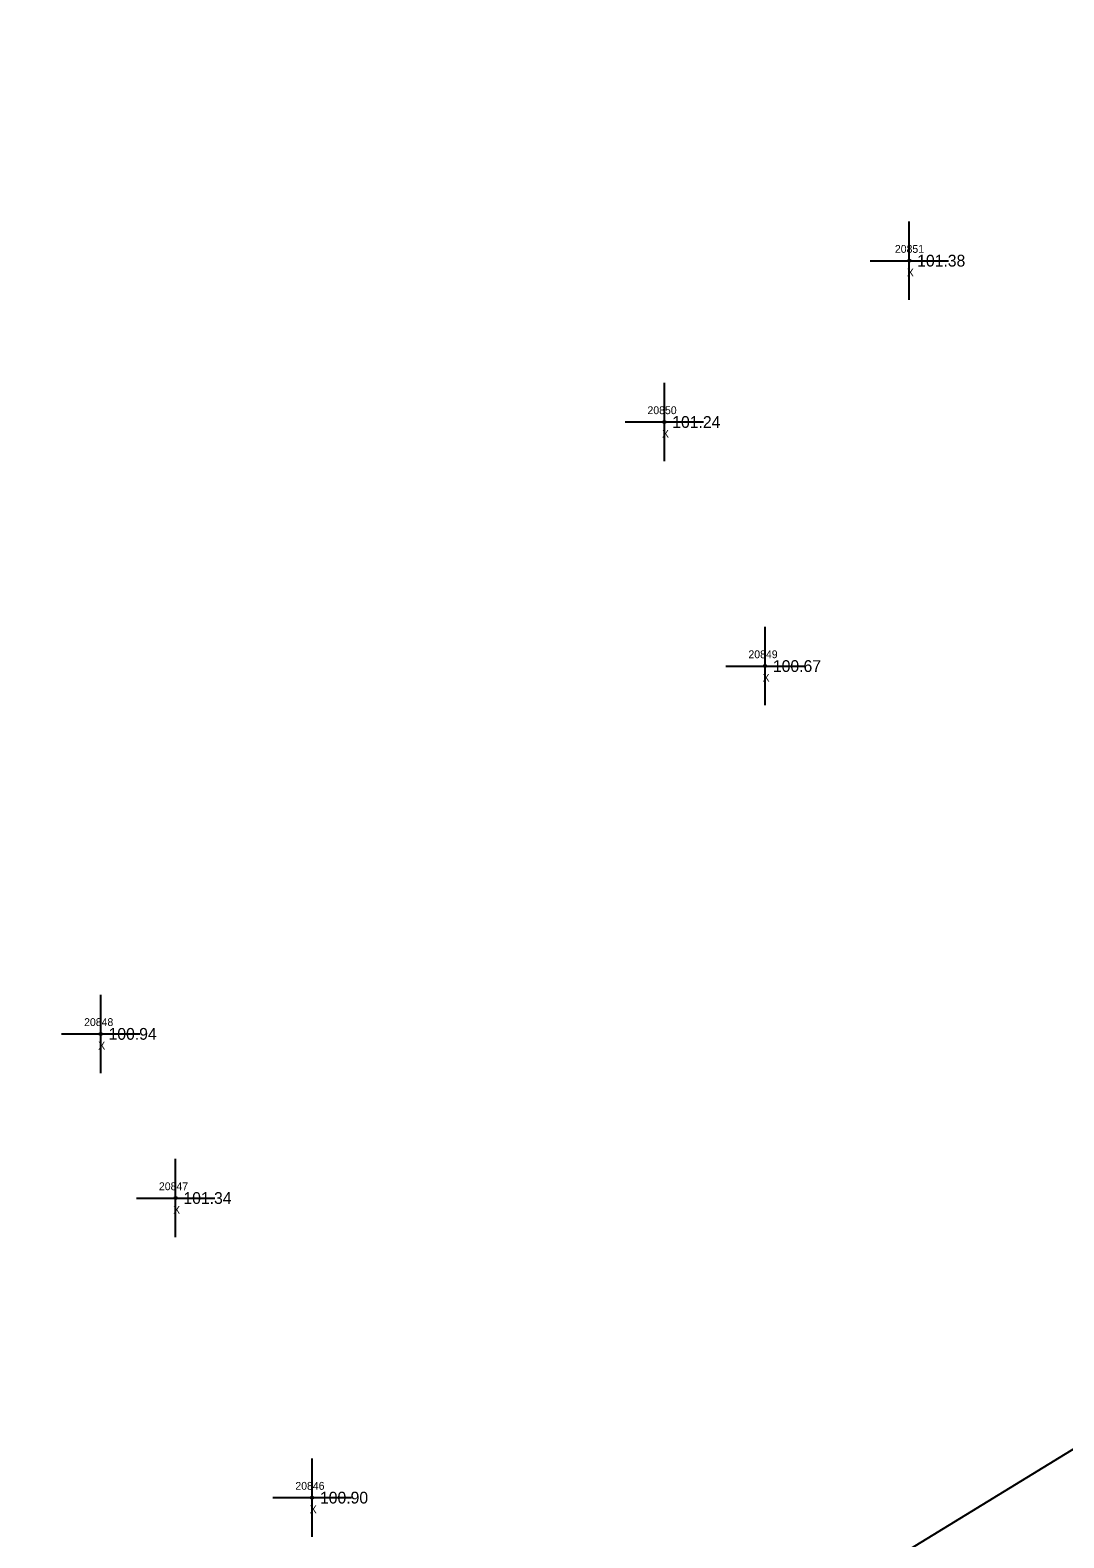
# Model space of a CAD drawing. Extents: x 2530197 to 2532051, y 935230 to 936631.
# Drawn here: x 2530638.9 to 2530770.7, y 935755.5 to 935947.8 of the extents above; entities that cross this region are included whole.
import ezdxf

# ---------------------------------------------------------------- set-up
doc = ezdxf.new("R2010")
doc.units = 0
for name, color, linetype in [('RD_EX_Misc', 7, 'Continuous'), ('RD_EX_Misc_txCode', 7, 'Continuous'), ('RD_EX_Road', 7, 'Continuous'), ('RD_EX_TX_Misc_ELEV', 7, 'Continuous'), ('RD_SMD_Locator', 7, 'Continuous')]:
    doc.layers.add(name, color=color, linetype=linetype)

msp = doc.modelspace()

# ---------------------------------------------------------------- linework, layer by layer
at = {"layer": 'RD_EX_Misc'}
for p, q in [((2530751.01, 935913.37), (2530751.01, 935923.37)), ((2530746.01, 935918.37), (2530756.01, 935918.37)), ((2530719.79, 935892.8), (2530719.79, 935902.8)), ((2530714.79, 935897.8), (2530724.79, 935897.8)), ((2530732.62, 935861.68), (2530732.62, 935871.68)), ((2530727.62, 935866.68), (2530737.62, 935866.68)), ((2530647.93, 935814.78), (2530647.93, 935824.78)), ((2530642.93, 935819.78), (2530652.93, 935819.78)), ((2530657.47, 935793.85), (2530657.47, 935803.85)), ((2530652.47, 935798.85), (2530662.47, 935798.85)), ((2530674.88, 935755.65), (2530674.88, 935765.65)), ((2530669.88, 935760.65), (2530679.88, 935760.65))]:
    msp.add_line(p, q, dxfattribs=at)
at = {"layer": 'RD_EX_Road'}
msp.add_lwpolyline([(2530213.13, 935600.16), (2530313.8, 935600.81), (2530414.15, 935601.13), (2530426.72, 935601.43), (2530429.46, 935603.55), (2530467.67, 935608.62), (2530486.46, 935612.38), (2530518.02, 935622.55), (2530522.16, 935623.68), (2530567.91, 935646.01), (2530609.3, 935670.15), (2530695.46, 935720.02), (2530775.85, 935769.27), (2530868.29, 935824.03), (2530924.84, 935856.95), (2530956.21, 935875.82), (2531040.72, 935926.38), (2531079.45, 935947.76)], dxfattribs=at)
at = {"layer": 'RD_SMD_Locator'}
for centre in [(2530751.01, 935918.37), (2530719.79, 935897.8), (2530732.62, 935866.68), (2530647.93, 935819.78), (2530657.47, 935798.85), (2530674.88, 935760.65)]:
    msp.add_circle(centre, 0.15, dxfattribs=at)

# ---------------------------------------------------------------- texts
at = {"layer": 'RD_EX_Misc_txCode'}
for s, p in [('20851', (2530749.17, 935919.37)), ('X', (2530750.69, 935916.37)), ('20850', (2530717.63, 935898.8)), ('X', (2530719.48, 935895.8)), ('20849', (2530730.5, 935867.68)), ('X', (2530732.31, 935864.68)), ('20848', (2530645.81, 935820.78)), ('X', (2530647.61, 935817.78)), ('20847', (2530655.35, 935799.85)), ('X', (2530657.16, 935796.85)), ('20846', (2530672.74, 935761.65)), ('X', (2530674.57, 935758.65))]:
    msp.add_text(s, height=1, dxfattribs=at).set_placement(p)
at = {"layer": 'RD_EX_TX_Misc_ELEV'}
for s, p in [('101.38', (2530752.01, 935917.62)), ('101.24', (2530720.79, 935897.05)), ('100.67', (2530733.62, 935865.93)), ('100.94', (2530648.93, 935819.03)), ('101.34', (2530658.47, 935798.1)), ('100.90', (2530675.88, 935759.9))]:
    msp.add_text(s, height=1.5, dxfattribs=at).set_placement(p)

doc.saveas('drawing.dxf')
